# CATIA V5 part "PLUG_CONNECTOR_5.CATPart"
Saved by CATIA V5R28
Part number: PLUG_CONNECTOR_5
Revision: --A
Publications: "MasterKeywayAxis", "InsertFrontFace", "InsertRearFace", "Logical Termination.1", "Logical Pin.1", "CCP", "Face_generated(CCP)", "Axis_generated(CCP)", "Face_generated(CCP).1", "BCP", "BCPRPoint_generated(BCP)", "BCPPlane_generated(BCP)", "BaCP", "Face_generated(BaCP)", "Axis_generated(BaCP)", "Face_generated(BaCP).1", "CaCP", "CaCPRPoint_generated(CaCP)", "Face_generated(CaCP)", "Axis_generated(CaCP)", "Face_generated(CaCP).1"
Bounding box of the stored display mesh (mm): x 0 to 34.1, y -12.1 to 12.1, z -12.09 to 12.09
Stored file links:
  C:\Users\ajc8720\Documents\BOEING_WORK\0001-2CES\004-AP242\Boeing-Generic_Harness_R3\PLUG_CONNECTOR_5.CATPart
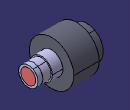
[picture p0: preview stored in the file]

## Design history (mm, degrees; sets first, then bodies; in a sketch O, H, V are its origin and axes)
Parameters
  PartNumber = "PLUG_CONNECTOR_5"
AxisSystem1 "MasterKeywayAxis": origin (0, 0, 0), X (1, 0, 0), Y (0, 1, 0), Z (0, 0, 1)
Set1 "EGF"
  Set2 "CCP"
    Point1 "CCPRPoint": (15.01 {= deleted_ShoulderFront}, 0, 0)
  Set3 "BaCP"
    Point2 "BaCPRPoint": (34 {= deleted_ShellLength}, 0, 0)
  Set4 "BCP"
    Plane1 "BCPPlane": type Offset, RefPlane face of Pad6, Offset 0, reversed
    Point3 "BCPRPoint": type OnPlane, Support Plane1, H 0, V 0, Direction (0, 1, 0)
  Set5 "CaCP"
    Point4 "CaCPRPoint": (15.01 {= deleted_ShoulderFront}, 0, 0)
    Plane2 "CaCPPlane": type OffsetPt, RefPlane yz-plane, RefPoint Point4
Body1 "CouplingRing" (main body)
  Sketch1 on yz-plane, origin (0, 0, 0), H (0, 1, 0), V (0, 0, 1)
    circle A1 centre (0, 0) radius 12.1
    radius A1 = 12.1
  Pad1 "CouplingRing": profile Sketch1, direction (1, 0, 0), length 21.38 {= deleted_CouplingRingFront + deleted_CouplingRingLength}, opposite side length -2 {= -( deleted_CouplingRingFront )}
  Sketch2 on zx-plane, origin (0, 0, 0), H (-1, 0, 0), V (0, 0, 1)
    line L1 (-7.5, 12.1) -> (-2, 12.1)
    line L2 (-2, 12.1) -> (-2, 8.9)
    line L3 (-2, 8.9) -> (-7.5, 8.9)
    line L4 (-7.5, 8.9) -> (-7.5, 12.1)
    distance H L3 = 8.9
    distance H L1 = 12.1
    distance V L2 = 2
    length L1 = 5.5
    horizontal: L1 H, L3 H
    vertical: L2 V, L4 V
  Groove1 "CouplingRingRelief": profile Sketch2, axis Sketch2.H, angle 360
  Sketch3 on face of Pad1, origin (2, 0, 0), H (0, -1, 0), V (0, 0, 1)
    point P1 (0, 0)
    reference intersected line E1 through (0, 0) direction (-1, 0) from xy-plane
    reference intersected line E2 through (0, 0) direction (0, -1) from zx-plane
    coincidence: P1 E1, P1 E2
  Hole1 "CouplingRingID": placed by Sketch3, at (2, 0, 0) direction (1, 0, 0), diameter 16.18 {= deleted_CouplingRingThreadDia}, depth 18.36 {= deleted_CouplingRingThreadLength}, counterbore diameter 16.51 {= deleted_CouplingRingFrontID}, counterbore depth 2.14 {= deleted_CouplingRingFrontIDLength}
  Sketch4 on face of Hole1, origin (20.36, 0, 0), H (0, 1, 0), V (0, 0, -1)
    point P1 (0, 0)
    reference intersected line E1 through (0, 0) direction (0, 1) from zx-plane
    reference intersected line E2 through (0, 0) direction (1, 0) from xy-plane
    coincidence: P1 E1, P1 E2
  Hole2 "CouplingRingThruHole": placed by Sketch4, at (20.36, 0, 0) direction (1, 0, 0), diameter 12.4 {= deleted_CouplingRingThruDia}, through (limit type 6)
Body2 "Shell"
  Sketch5 on yz-plane, origin (0, 0, 0), H (0, 1, 0), V (0, 0, 1)
    circle A1 centre (0, 0) radius 5.55
    radius A1 = 5.55
  Pad2 "ShellFront": profile Sketch5, direction (1, 0, 0), length 15.01 {= deleted_ShoulderFront}
  Sketch6 on yz-plane, origin (0, 0, 0), H (0, 1, 0), V (0, 0, 1)
    circle A1 centre (0, 0) radius 6
    radius A1 = 6
  Pad3 "ShellBack": profile Sketch6, direction (1, 0, 0), length 34 {= deleted_ShellLength}, opposite side length -15.01 {= -( deleted_ShoulderFront )}
  Sketch7 on zx-plane, origin (0, 0, 0), H (-1, 0, 0), V (0, 0, 1)
    line L1 (-34, 6) -> (-26.89, 6)
    line L2 (-31.34, 5.3) -> (-31.34, 5.285)
    line L3 (-31.34, 5.285) -> (-34, 5.285)
    line L4 (-34, 5.285) -> (-34, 6)
    line L5 (-26.89, 6) -> (-26.89, 5.3)
    line L6 (-26.89, 5.3) -> (-31.34, 5.3)
    distance V L4 = 34 {= deleted_ShellLength}
    length L1 = 7.11 {= deleted_AccThreadLength}
    length L3 = 2.66 {= deleted_ShellRearODLength}
    distance H L3 = 5.285 {= deleted_ShellRearOD / 2}
    distance H L6 = 5.3 {= deleted_AccThreadDia / 2}
    distance L1 H = 6
    horizontal: L1 H, L3 H, L6 H
    vertical: L2 V, L4 V, L5 V
  Groove2 "AccyTeethThread": profile Sketch7, axis Sketch7.H, angle 360
  Sketch8 on yz-plane, origin (0, 0, 0), H (0, 1, 0), V (0, 0, 1)
    point P1 (-1.575, 0)
    line L1 (-1.575, 0) -> (1.575, 0)
    line L2 (1.575, 0) -> (1.575, 6)
    line L3 (1.575, 6) -> (-1.575, 6)
    line L4 (-1.575, 6) -> (-1.575, 0)
    length L3 = 3.15
    distance H L3 = 6
    coincidence: P1 H
    horizontal: L1 H, L3 H
    vertical: L2 V, L4 V
    symmetry: L2 L4 V
  Pad4 "MasterKeyway": profile Sketch8, direction (1, 0, 0), length 15.01 {= deleted_ShoulderFront}, opposite side length -0.76 {= - ( deleted_MasterKeyFront )}
  Sketch9 on face of Pad2, origin (0, 0, 0), H (0, -1, 0), V (0, 0, 1)
    point P1 (0, 0)
    reference intersected line E1 through (0, 0) direction (0, -1) from zx-plane
    reference intersected line E2 through (0, 0) direction (-1, 0) from xy-plane
    coincidence: P1 E1, P1 E2
  Hole3 "FrontShellID": placed by Sketch9, at (0, 0, 0) direction (1, 0, 0), diameter 10 {= deleted_ShellFrontID}, depth 23.46 {= deleted_ShellLength - deleted_ShellRearIDLength}
  Sketch10 on face of Pad3, origin (34, 0, 0), H (0, 1, 0), V (0, 0, 1)
    point P1 (0, 0)
    reference intersected line E1 through (0, 0) direction (0, 1) from zx-plane
    reference intersected line E2 through (0, 0) direction (-1, 0) from xy-plane
    coincidence: P1 E1, P1 E2
  Hole4 "RearShellID": placed by Sketch10, at (34, 0, 0) direction (-1, 0, 0), diameter 8.8 {= deleted_ShellRearID}, depth 10.54 {= deleted_ShellRearIDLength}
Body3 "Insert"
  Sketch11 on yz-plane, origin (0, 0, 0), H (0, 1, 0), V (0, 0, 1)
    circle A1 centre (0, 0) radius 4.925
    radius A1 = 4.925
  Pad5 "InsertOD": profile Sketch11, direction (1, 0, 0), length 21.4 {= deleted_InsertFront + deleted_InsertLength - deleted_GrommetLength}, opposite side length -0.1 {= -( deleted_InsertFront )}
  Sketch12 on yz-plane, origin (0, 0, 0), H (0, 1, 0), V (0, 0, 1)
    circle A1 centre (0, 0) radius 4.1
    radius A1 = 4.1
  Pad6 "GrommetOD": profile Sketch12, direction (1, 0, 0), length 34.1 {= deleted_InsertFront + deleted_InsertLength}, opposite side length -21.4 {= -( deleted_InsertFront + deleted_InsertLength - deleted_GrommetLength )}
Body4 "CaCP"
  Sketch13 "Sketch" on Plane2, origin (15.01, 0, 0), H (0, 1, 0), V (0, 0, 1)
    line L1 (-0.672, 0.762) -> (0.672, 0.762)
    point P1 (-0.672, 0.762)
    point P2 (0.672, 0.762)
    arc A1 centre (0, 0) radius 1.016 from (-1.016, 0) to (1.016, 0) ccw
    point P3 (0, 0)
    point P4 (-1.016, 0)
    point P5 (1.016, 0)
    reference projected point E1 (0, 0) from Point4
    arc A2 centre (0, 0) radius 1.016 from (1.016, 0) to (0.672, 0.762) ccw
    point P6 (0, 0)
    point P7 (1.016, 0)
    point P8 (0.672, 0.762)
    arc A3 centre (0, 0) radius 1.016 from (-0.672, 0.762) to (-1.016, 0) ccw
    point P9 (0, 0)
    point P10 (-0.672, 0.762)
    point P11 (-1.016, 0)
    reference projected point E2 (0, 0) from Point4
    reference projected point E3 (0, 0) from Point4
    length L1 = 1.344
    radius A1 = 1.016
    radius A3 = 1.016
    radius A2 = 1.016
    distance L1 P5 = 0.762
    distance P4 L1 = 0.762
    distance P7 L1 = 0.762
    distance P11 L1 = 0.762
    coincidence: P3 E1, P6 E2, P9 E3, P8 P2, P10 P1
    horizontal: L1 H
  Pad7: profile Sketch13, direction (1, 0, 0), length 0.508, opposite side up to Plane2
Body5 "CCP"
  Sketch14 on face of Pad3, origin (15.01, 0, 0), H (0, 1, 0), V (0, 0, 1)
    arc A1 centre (0, 0) radius 1.016 from (-0.672, 0.762) to (0.672, 0.762) ccw
    line L1 (-0.672, 0.762) -> (0.672, 0.762)
    distance L1 H = 0.762
    radius A1 = 1.016
  Pad8: profile Sketch14, direction (1, 0, 0), length 0.508
Body6 "BaCP"
  Sketch15 on face of Pad3, origin (34, 0, 0), H (0, 1, 0), V (0, 0, 1)
    arc A1 centre (0, 0) radius 1.016 from (-0.672, 0.762) to (0.672, 0.762) ccw
    line L1 (-0.672, 0.762) -> (0.672, 0.762)
    distance L1 H = 0.762
    radius A1 = 1.016
  Sketch16 on face of Pad3, origin (34, 0, 0), H (0, 1, 0), V (0, 0, 1)
    circle A1 centre (0, 0) radius 1.27
    radius A1 = 1.27
  Pad9: profile Sketch16, direction (1, 0, 0), length 0.254, opposite side length 0.254
  Pocket1: profile Sketch15, direction (1, 0, 0), through (limit type 6)
Current feature: Hole3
